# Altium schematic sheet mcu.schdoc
size 277 x 190 mm; Device: default297x210; Symbol: default297x210; Name: default297x210; Size: "A4"; Id: /; File: mcu; Sheet: /
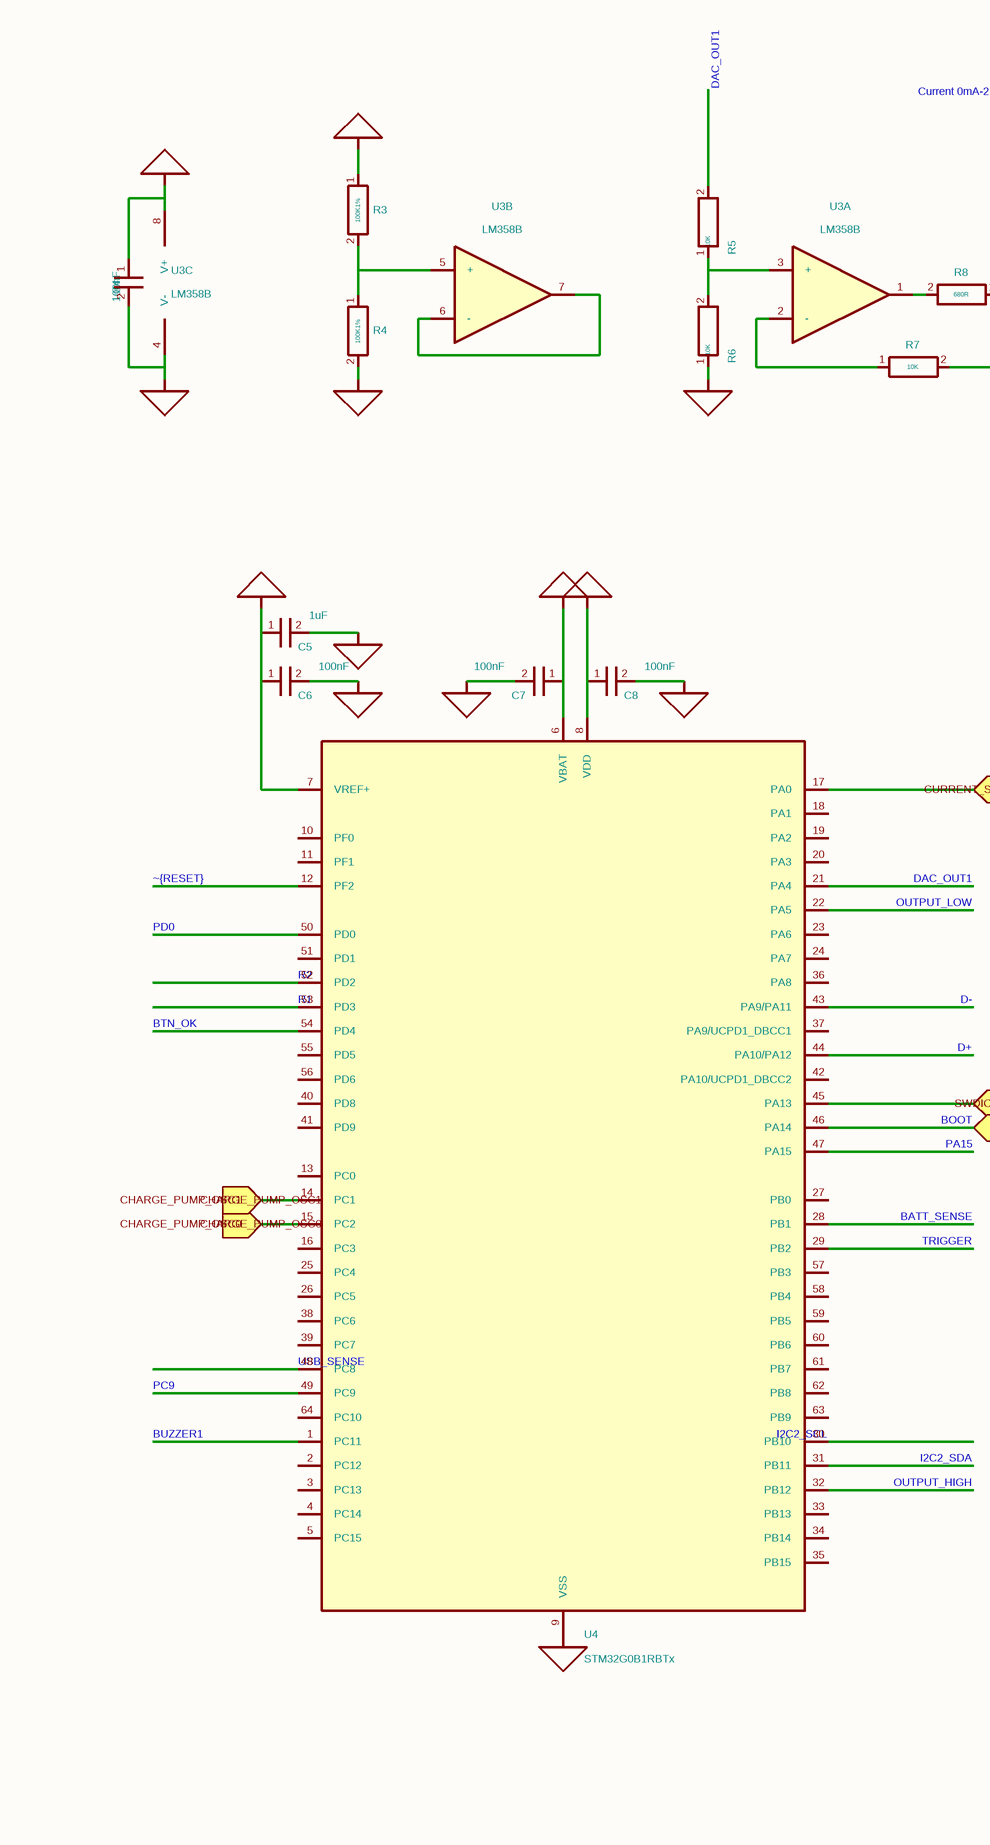
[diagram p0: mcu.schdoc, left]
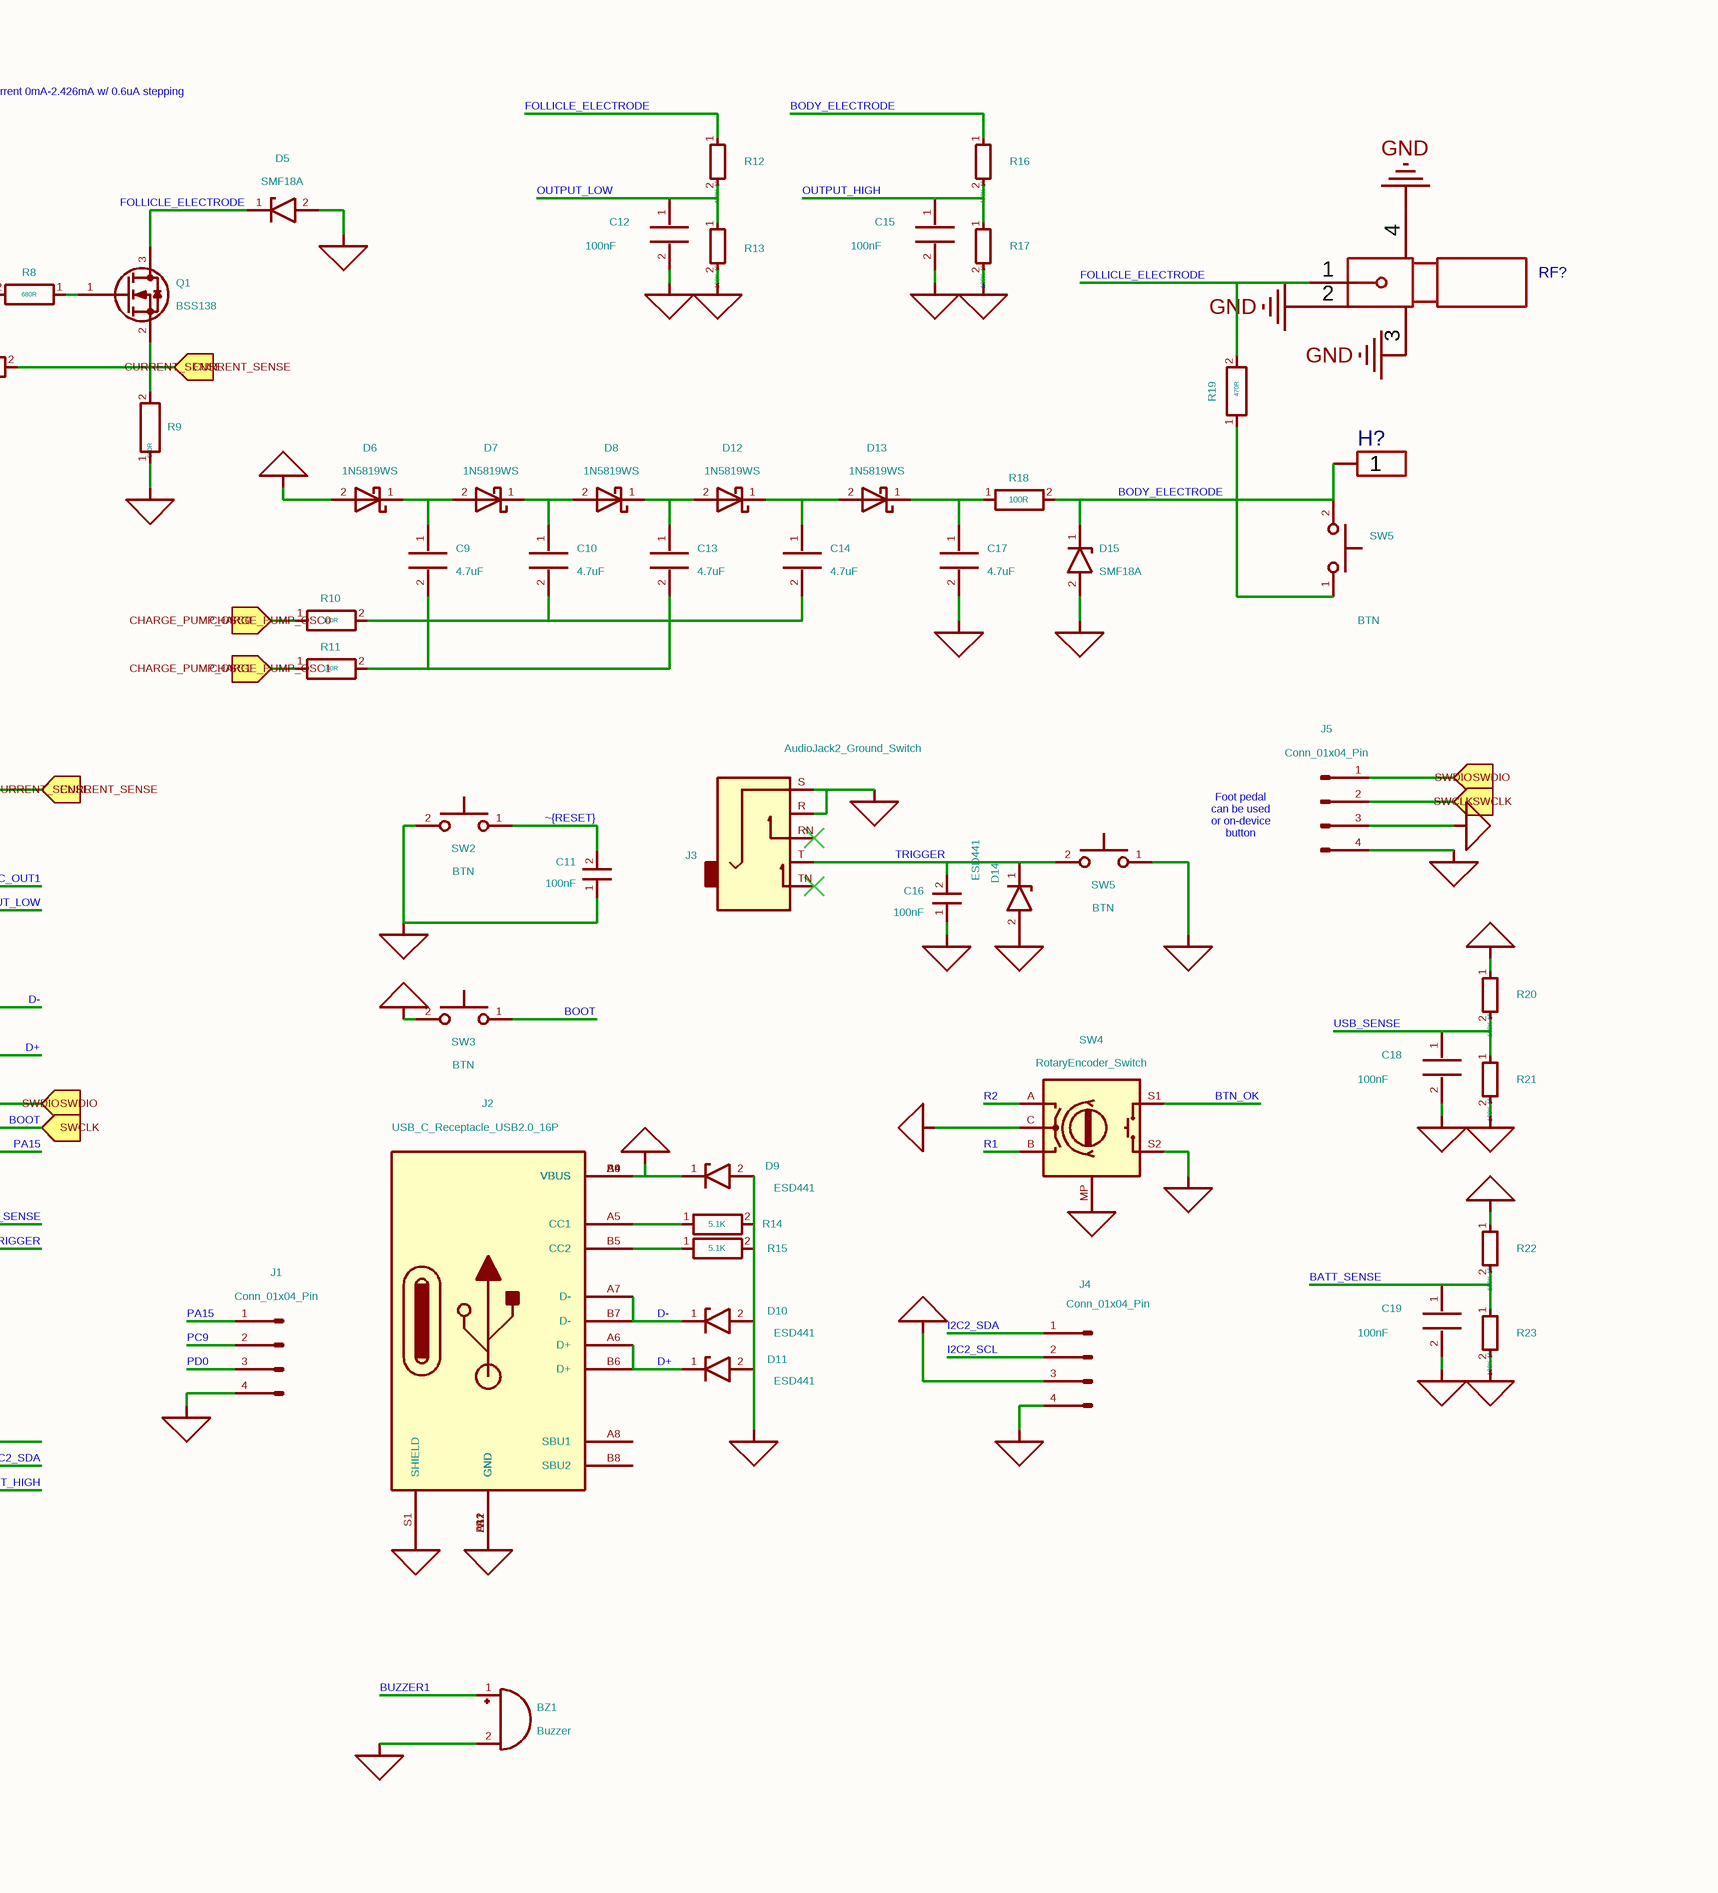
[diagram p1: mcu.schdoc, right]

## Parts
(Parts that share a designator on the sheet are numbered #1, #2 ... from top to bottom, then left to right.)
BZ1  value Buzzer  [Buzzer_Beeper:Buzzer_TDK_PS1240P02BT_D12.2mm_H6.5mm]  (hidden comment: Device_Buzzer)
C4  value 100nF  [Capacitor_SMD:C_0603_1608Metric]  (hidden comment: Device_C_Small)
C5  value 1uF  [Capacitor_SMD:C_0603_1608Metric]  (hidden comment: Device_C_Small)
C6  value 100nF  [Capacitor_SMD:C_0603_1608Metric]  (hidden comment: Device_C_Small)
C7  value 100nF  [Capacitor_SMD:C_0603_1608Metric]  (hidden comment: Device_C_Small)
C8  value 100nF  [Capacitor_SMD:C_0603_1608Metric]  (hidden comment: Device_C_Small)
C9  value 4.7uF  [Capacitor_SMD:C_0805_2012Metric]  (hidden comment: Device_C)
C10  value 4.7uF  [Capacitor_SMD:C_0805_2012Metric]  (hidden comment: Device_C)
C11  value 100nF  [Capacitor_SMD:C_0603_1608Metric]  (hidden comment: Device_C_Small)
C12  value 100nF  [Capacitor_SMD:C_0603_1608Metric]  (hidden comment: Device_C)
C13  value 4.7uF  [Capacitor_SMD:C_0805_2012Metric]  (hidden comment: Device_C)
C14  value 4.7uF  [Capacitor_SMD:C_0805_2012Metric]  (hidden comment: Device_C)
C15  value 100nF  [Capacitor_SMD:C_0603_1608Metric]  (hidden comment: Device_C)
C16  value 100nF  [Capacitor_SMD:C_0603_1608Metric]  (hidden comment: Device_C_Small)
C17  value 4.7uF  [Capacitor_SMD:C_0805_2012Metric]  (hidden comment: Device_C)
C18  value 100nF  [Capacitor_SMD:C_0603_1608Metric]  (hidden comment: Device_C)
C19  value 100nF  [Capacitor_SMD:C_0603_1608Metric]  (hidden comment: Device_C)
D5  value SMF18A  [Diode_SMD:D_SMF]  (hidden comment: Diode_SMF18A)
D6  value 1N5819WS  [Diode_SMD:D_SOD-323]  (hidden comment: Diode_1N5819WS)
D7  value 1N5819WS  [Diode_SMD:D_SOD-323]  (hidden comment: Diode_1N5819WS)
D8  value 1N5819WS  [Diode_SMD:D_SOD-323]  (hidden comment: Diode_1N5819WS)
D9  value ESD441  [Diode_SMD:D_0402_1005Metric]  (hidden comment: Diode_SM6T7V5A)
D10  value ESD441  [Diode_SMD:D_0402_1005Metric]  (hidden comment: Diode_SM6T7V5A)
D11  value ESD441  [Diode_SMD:D_0402_1005Metric]  (hidden comment: Diode_SM6T7V5A)
D12  value 1N5819WS  [Diode_SMD:D_SOD-323]  (hidden comment: Diode_1N5819WS)
D13  value 1N5819WS  [Diode_SMD:D_SOD-323]  (hidden comment: Diode_1N5819WS)
D14  value ESD441  [Diode_SMD:D_0402_1005Metric]  (hidden comment: Diode_SM6T7V5A)
D15  value SMF18A  [Diode_SMD:D_SMF]  (hidden comment: Diode_SMF18A)
H?  (no value)  [HDR-TH_1P-V-M_XKB_X4611WV-01I-C28D40]
J1  value Conn_01x04_Pin  [Connector_PinHeader_2.54mm:PinHeader_1x04_P2.54mm_Vertical]  (hidden comment: Connector_Conn_01x04_Pin)
J2  value USB_C_Receptacle_USB2.0_16P  [Connector_USB:USB_C_Receptacle_HRO_TYPE-C-31-M-12]  (hidden comment: Connector_USB_C_Receptacle_USB2.0_16P)
J3  value AudioJack2_Ground_Switch  [Connector_Audio:Jack_3.5mm_CUI_SJ1-3525N_Horizontal]  (hidden comment: Connector_Audio_AudioJack3_SwitchTR)
J4  value Conn_01x04_Pin  [Connector_PinSocket_2.54mm:PinSocket_1x04_P2.54mm_Vertical]  (hidden comment: Connector_Conn_01x04_Pin)
J5  value Conn_01x04_Pin  [Connector_PinSocket_2.54mm:PinSocket_1x04_P2.54mm_Vertical]  (hidden comment: Connector_Conn_01x04_Pin)
Q1  value BSS138  [Package_TO_SOT_SMD:SOT-23]  (hidden comment: Transistor_FET_BSS138)
R3  value 100K1%  [Resistor_SMD:R_0603_1608Metric_Pad0.98x0.95mm_HandSolder]  (hidden comment: Device_R)
R4  value 100K1%  [Resistor_SMD:R_0603_1608Metric_Pad0.98x0.95mm_HandSolder]  (hidden comment: Device_R)
R5  value 10K  [Resistor_SMD:R_0603_1608Metric_Pad0.98x0.95mm_HandSolder]  (hidden comment: Device_R)
R6  value 10K  [Resistor_SMD:R_0603_1608Metric_Pad0.98x0.95mm_HandSolder]  (hidden comment: Device_R)
R7  value 10K  [Resistor_SMD:R_0603_1608Metric_Pad0.98x0.95mm_HandSolder]  (hidden comment: Device_R)
R8  value 680R  [Resistor_SMD:R_0603_1608Metric_Pad0.98x0.95mm_HandSolder]  (hidden comment: Device_R)
R9  value 680R  [Resistor_SMD:R_0603_1608Metric_Pad0.98x0.95mm_HandSolder]  (hidden comment: Device_R)
R10  value 100R  [Resistor_SMD:R_0603_1608Metric]  (hidden comment: Device_R)
R11  value 100R  [Resistor_SMD:R_0603_1608Metric]  (hidden comment: Device_R)
R12  value 470K 1%  [Resistor_SMD:R_0603_1608Metric]  (hidden comment: Device_R_Small)
R13  value 100K 1%  [Resistor_SMD:R_0603_1608Metric]  (hidden comment: Device_R_Small)
R14  value 5.1K  [Resistor_SMD:R_0603_1608Metric]  (hidden comment: Device_R)
R15  value 5.1K  [Resistor_SMD:R_0603_1608Metric]  (hidden comment: Device_R)
R16  value 470K 1%  [Resistor_SMD:R_0603_1608Metric]  (hidden comment: Device_R_Small)
R17  value 100K 1%  [Resistor_SMD:R_0603_1608Metric]  (hidden comment: Device_R_Small)
R18  value 100R  [Resistor_SMD:R_0603_1608Metric]  (hidden comment: Device_R)
R19  value 470R  [Resistor_SMD:R_0603_1608Metric_Pad0.98x0.95mm_HandSolder]  (hidden comment: Device_R)
R20  value 100K 1%  [Resistor_SMD:R_0603_1608Metric]  (hidden comment: Device_R_Small)
R21  value 100K 1%  [Resistor_SMD:R_0603_1608Metric]  (hidden comment: Device_R_Small)
R22  value 100K 1%  [Resistor_SMD:R_0603_1608Metric]  (hidden comment: Device_R_Small)
R23  value 100K 1%  [Resistor_SMD:R_0603_1608Metric]  (hidden comment: Device_R_Small)
RF?  3GHz  [BNC-TH_DOSIN-801-0030]  (value not drawn)
SW2  value BTN  [Button_Switch_SMD:SW_SPST_TS-1088-xR025]  (hidden comment: Switch_SW_Push)
SW3  value BTN  [Button_Switch_SMD:SW_SPST_TS-1088-xR025]  (hidden comment: Switch_SW_Push)
SW4  value RotaryEncoder_Switch  [Rotary_Encoder:RotaryEncoder_Alps_EC11E-Switch_Vertical_H20mm]  (hidden comment: Device_RotaryEncoder_Switch)
SW5#1  value BTN  [Button_Switch_SMD:SW_SPST_TS-1088-xR025]  (hidden comment: Switch_SW_Push)
SW5#2  value BTN  [Button_Switch_SMD:SW_SPST_TS-1088-xR025]  (hidden comment: Switch_SW_Push)
U3  value LM358B  [Package_SO:SOIC-8_3.9x4.9mm_P1.27mm]  (hidden comment: Amplifier_Operational_LM358)  (parts A,B,C of 3)
U4  value STM32G0B1RBTx  [Package_QFP:LQFP-64_10x10mm_P0.5mm]  (hidden comment: MCU_ST_STM32G0_STM32G0B1RBTx)

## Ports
CHARGE_PUMP_OSC0 (in), CHARGE_PUMP_OSC1 (in), CURRENT_SENSE (in), SWCLK (in), SWDIO (in)

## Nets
GND: RF?.2 RF?.3 RF?.4
power_+3.3V: C5.1 C6.1 C7.1 C8.1 D6.2(A) J4.3(Pin_3) J5.3(Pin_3) SW3.2 U4.6(VBAT) U4.7(VREF+) U4.8(VDD)
power_+5V: D9.1(A1) J2.A4(VBUS) J2.A9(VBUS) J2.B4(VBUS) J2.B9(VBUS)
power_+BATT: C4.1 R3.1 R22.1 U3.8(V+)
power_GND: BZ1.2(-) C4.2 C5.2 C6.2 C7.2 C8.2 C11.1 C12.2 C15.2 C16.1 C17.2 C18.2 C19.2 D5.2(A2) D9.2(A2) D10.2(A2) D11.2(A2) D14.2(A2) D15.2(A2) J1.4(Pin_4) J2.A1(GND) J2.A12(GND) J2.B1(GND) J2.B12(GND) J2.S1(SHIELD) J3.R J3.S J4.4(Pin_4) J5.4(Pin_4) R4.2 R6.1 R9.1 R13.2 R14.2 R15.2 R17.2 R21.2 R23.2 SW2.2 SW4.C SW4.MP SW4.S2 SW5#2.1 U3.4(V-) U4.9(VSS)
power_VBUS: R20.1
BATT_SENSE: C19.1 R22.2 R23.1 U4.28(PB1)
BODY_ELECTRODE: D15.1(A1) H?.1 R16.1 R18.2 SW5#1.2
BOOT: J5.2(Pin_2) SW3.1 U4.46(PA14) ; port SWCLK  [also labelled SWCLK]
BTN_OK: SW4.S1 U4.54(PD4)
BUZZER1: BZ1.1(+) U4.1(PC11)
CHARGE_PUMP_OSC0: R10.1 U4.15(PC2) ; port CHARGE_PUMP_OSC0
CHARGE_PUMP_OSC1: R11.1 U4.14(PC1) ; port CHARGE_PUMP_OSC1
CURRENT_SENSE: Q1.2(S) R7.2 R9.2 U4.17(PA0) ; port CURRENT_SENSE
D+: D11.1(A1) J2.A6(D+) J2.B6(D+) U4.44(PA10/PA12)
D-: D10.1(A1) J2.A7(D-) J2.B7(D-) U4.43(PA9/PA11)
DAC_OUT1: R5.2 U4.21(PA4)
FOLLICLE_ELECTRODE: D5.1(A1) Q1.3(D) R12.1 R19.2 RF?.1
I2C2_SCL: J4.2(Pin_2) U4.30(PB10)
I2C2_SDA: J4.1(Pin_1) U4.31(PB11)
OUTPUT_HIGH: C15.1 R16.2 R17.1 U4.32(PB12)
OUTPUT_LOW: C12.1 R12.2 R13.1 U4.22(PA5)
PA15: J1.1(Pin_1) U4.47(PA15)
PC9: J1.2(Pin_2) U4.49(PC9)
PD0: J1.3(Pin_3) U4.50(PD0)
R1: SW4.B U4.53(PD3)
R2: SW4.A U4.52(PD2)
SWDIO: J5.1(Pin_1) U4.45(PA13) ; port SWDIO
TRIGGER: C16.2 D14.1(A1) J3.T SW5#2.2 U4.29(PB2)
USB_SENSE: C18.1 R20.2 R21.1 U4.48(PC8)
~{RESET}: C11.2 SW2.1 U4.12(PF2)
NetC9_1: C9.1 D6.1(K) D7.2(A)
NetC9_2: C9.2 C13.2 R11.2
NetC10_1: C10.1 D7.1(K) D8.2(A)
NetC10_2: C10.2 C14.2 R10.2
NetC13_1: C13.1 D8.1(K) D12.2(A)
NetC14_1: C14.1 D12.1(K) D13.2(A)
NetC17_1: C17.1 D13.1(K) R18.1
NetJ2_A5: J2.A5(CC1) R14.1
NetJ2_B5: J2.B5(CC2) R15.1
NetQ1_1: Q1.1(G) R8.1
NetR3_2: R3.2 R4.1 U3.5(+)
NetR5_1: R5.1 R6.2 U3.3(+)
NetR7_1: R7.1 U3.2(-)
NetR8_2: R8.2 U3.1
NetR19_1: R19.1 SW5#1.1
NetU3_6: U3.6(-) U3.7

Not connected (* = marked no-connect by the designer): J2 A8(SBU1) B8(SBU2); J3 RN* TN*; U4 2(PC12) 3(PC13) 4(PC14) 5(PC15) 10(PF0) 11(PF1) 13(PC0) 16(PC3) 18(PA1) 19(PA2) 20(PA3) 23(PA6) 24(PA7) 25(PC4) 26(PC5) 27(PB0) 33(PB13) 34(PB14) 35(PB15) 36(PA8) 37(PA9/UCPD1_DBCC1) 38(PC6) 39(PC7) 40(PD8) 41(PD9) 42(PA10/UCPD1_DBCC2) 51(PD1) 55(PD5) 56(PD6) 57(PB3) 58(PB4) 59(PB5) 60(PB6) 61(PB7) 62(PB8) 63(PB9) 64(PC10)

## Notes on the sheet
- Current 0mA-2.426mA w/ 0.6uA stepping
- Foot pedal
  can be used
  or on-device
  button

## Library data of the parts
BZ1 = Device_Buzzer: ki_fp_filters: *Buzzer*; UniqueId: a79a1bda820114ad; Attribute1: BZ1; AddInBom: yes
C4 = Device_C_Small: Unpolarized capacitor, small symbol; ki_fp_filters: C_*; UniqueId: 3a68d3ddabf48558; Attribute1: C6; AddInBom: yes
C5 = Device_C_Small: Unpolarized capacitor, small symbol; ki_fp_filters: C_*; UniqueId: ddba3c46cf8b8e66; Attribute1: C6; AddInBom: yes
C6 = Device_C_Small: Unpolarized capacitor, small symbol; ki_fp_filters: C_*; UniqueId: ab4a8fe24fad9fe4; Attribute1: C6; AddInBom: yes
C7 = Device_C_Small: Unpolarized capacitor, small symbol; ki_fp_filters: C_*; UniqueId: 48d2dd422533522c; Attribute1: C6; AddInBom: yes
C8 = Device_C_Small: Unpolarized capacitor, small symbol; ki_fp_filters: C_*; UniqueId: 80f3708378e3d903; Attribute1: C6; AddInBom: yes
C9 = Device_C: Unpolarized capacitor; UniqueId: 7ddfd2f632a8b17d; AddInBom: yes
C10 = Device_C: Unpolarized capacitor; UniqueId: 3e75135af30e0f04; AddInBom: yes
C11 = Device_C_Small: Unpolarized capacitor, small symbol; ki_fp_filters: C_*; UniqueId: 20764de07767b3a1; Attribute1: C6; AddInBom: yes
C12 = Device_C: Unpolarized capacitor; UniqueId: 26a39bcafcc8ce7c; AddInBom: yes
C13 = Device_C: Unpolarized capacitor; UniqueId: e7ba3aba9f9889c8; AddInBom: yes
C14 = Device_C: Unpolarized capacitor; UniqueId: 00361082df9d4549; AddInBom: yes
C15 = Device_C: Unpolarized capacitor; UniqueId: 86bb77bda672094d; AddInBom: yes
C16 = Device_C_Small: Unpolarized capacitor, small symbol; ki_fp_filters: C_*; UniqueId: c8e923f96b539988; Attribute1: C6; AddInBom: yes
C17 = Device_C: Unpolarized capacitor; UniqueId: 48700c84863a802e; AddInBom: yes
C18 = Device_C: Unpolarized capacitor; UniqueId: d9d0285421fe3ef0; AddInBom: yes
C19 = Device_C: Unpolarized capacitor; UniqueId: 9b75bd895f0e39d2; AddInBom: yes
D5 = Diode_SMF18A: 200W unidirectional Transil Transient Voltage Suppressor, 18Vrwm, SMF; ki_fp_filters: D*SMF*; UniqueId: aa27cf4c2f614704; Attribute1: D15; AddInBom: yes
D6 = Diode_1N5819WS: 40V 600mV@1A 1A SOD-323 Schottky Barrier Diodes, SOD-323; ki_fp_filters: D*SOD?323*; UniqueId: 0b466d7a0d9696a1; Attribute1: D6; AddInBom: yes
D7 = Diode_1N5819WS: 40V 600mV@1A 1A SOD-323 Schottky Barrier Diodes, SOD-323; ki_fp_filters: D*SOD?323*; UniqueId: 61ba849a9213f6b6; Attribute1: D6; AddInBom: yes
D8 = Diode_1N5819WS: 40V 600mV@1A 1A SOD-323 Schottky Barrier Diodes, SOD-323; ki_fp_filters: D*SOD?323*; UniqueId: d726a396729c3148; Attribute1: D6; AddInBom: yes
D9 = Diode_SM6T7V5A: ki_fp_filters: D*SMB*; UniqueId: ff0c81595de38f51; Attribute1: D9; AddInBom: yes
D10 = Diode_SM6T7V5A: ki_fp_filters: D*SMB*; UniqueId: 260e63abbc5bbcdd; Attribute1: D9; AddInBom: yes
D11 = Diode_SM6T7V5A: ki_fp_filters: D*SMB*; UniqueId: 63002c75ba05748a; Attribute1: D9; AddInBom: yes
D12 = Diode_1N5819WS: 40V 600mV@1A 1A SOD-323 Schottky Barrier Diodes, SOD-323; ki_fp_filters: D*SOD?323*; UniqueId: a80f7d1f54f711b8; Attribute1: D6; AddInBom: yes
D13 = Diode_1N5819WS: 40V 600mV@1A 1A SOD-323 Schottky Barrier Diodes, SOD-323; ki_fp_filters: D*SOD?323*; UniqueId: d3460379f3d05a2a; Attribute1: D6; AddInBom: yes
D14 = Diode_SM6T7V5A: ki_fp_filters: D*SMB*; UniqueId: f1c346e37d3cba37; Attribute1: D9; AddInBom: yes
D15 = Diode_SMF18A: 200W unidirectional Transil Transient Voltage Suppressor, 18Vrwm, SMF; ki_fp_filters: D*SMF*; UniqueId: ff96faf82be08131; Attribute1: D15; AddInBom: yes
H? = HDR-M_2.54_1x1P: Symbol: HDR_1x1; AddInBom: yes; ModelId: 728f8802f5b64d9eac2f12b79a6c354c0819f05c4eef4c71ace90d822a990e87; ModelTransform: 78.74,79.1337,0,0,0,0,0,0,-110.236
J1 = Connector_Conn_01x04_Pin: Generic connector, single row, 01x04, script generated; ki_fp_filters: Connector*:*_1x??_*; UniqueId: 51bfc0e5166a1c40; Attribute1: J1; AddInBom: yes
J2 = Connector_USB_C_Receptacle_USB2.0_16P: USB 2.0-only 16P Type-C Receptacle connector; ki_fp_filters: USB*C*Receptacle*; UniqueId: 1fb9863844ab5169; Attribute1: J2; AddInBom: yes
J3 = Connector_Audio_AudioJack3_SwitchTR: Audio Jack, 3 Poles (Stereo / TRS), Switched TR Poles (Normalling); ki_fp_filters: Jack*; UniqueId: bd3ee0abdb58119f; Attribute1: PCB edge; Attribute2: J3; AddInBom: yes
J4 = Connector_Conn_01x04_Pin: Generic connector, single row, 01x04, script generated; ki_fp_filters: Connector*:*_1x??_*; UniqueId: 7aadee231938cadd; Attribute1: J4; KiLib_Generator: connector/pin_header_socket; AddInBom: yes
J5 = Connector_Conn_01x04_Pin: Generic connector, single row, 01x04, script generated; ki_fp_filters: Connector*:*_1x??_*; UniqueId: 188f82074eb8ca32; Attribute1: J4; KiLib_Generator: connector/pin_header_socket; AddInBom: yes
Q1 = Transistor_FET_BSS138: 50V Vds, 0.22A Id, N-Channel MOSFET, SOT-23; ki_fp_filters: SOT?23*; UniqueId: f76c01de5337d462; Attribute1: Q1; AddInBom: yes
R3 = Device_R: Resistor; ki_fp_filters: R_*; UniqueId: fe89d0632cfce75f; Attribute1: R7; KiLib_Generator: SMD_2terminal_chip_molded; AddInBom: yes
R4 = Device_R: Resistor; ki_fp_filters: R_*; UniqueId: fdc86a4b576d9e98; Attribute1: R7; KiLib_Generator: SMD_2terminal_chip_molded; AddInBom: yes
R5 = Device_R: Resistor; ki_fp_filters: R_*; UniqueId: 9cdd622c9eeecfe7; Attribute1: R7; KiLib_Generator: SMD_2terminal_chip_molded; AddInBom: yes
R6 = Device_R: Resistor; ki_fp_filters: R_*; UniqueId: e06ccd13940482ac; Attribute1: R7; KiLib_Generator: SMD_2terminal_chip_molded; AddInBom: yes
R7 = Device_R: Resistor; ki_fp_filters: R_*; UniqueId: ba2c6d155e7fd301; Attribute1: R7; KiLib_Generator: SMD_2terminal_chip_molded; AddInBom: yes
R8 = Device_R: Resistor; ki_fp_filters: R_*; UniqueId: 86d447fa2a9c8586; Attribute1: R7; KiLib_Generator: SMD_2terminal_chip_molded; AddInBom: yes
R9 = Device_R: Resistor; ki_fp_filters: R_*; UniqueId: 1e1ffada38203b9e; Attribute1: R7; KiLib_Generator: SMD_2terminal_chip_molded; AddInBom: yes
R10 = Device_R: Resistor; UniqueId: 41bc0941336b1513; AddInBom: yes
R11 = Device_R: Resistor; UniqueId: 763cf8d5648cb4fd; AddInBom: yes
R12 = Device_R_Small: Resistor, small symbol; ki_fp_filters: R_*; UniqueId: 15ac9218146e0f4b; Attribute1: R16; AddInBom: yes
R13 = Device_R_Small: Resistor, small symbol; ki_fp_filters: R_*; UniqueId: ff4077a9ca69db92; Attribute1: R16; AddInBom: yes
R14 = Device_R: Resistor; UniqueId: 8b54177fc4d64d35; AddInBom: yes
R15 = Device_R: Resistor; UniqueId: feece054417b9159; AddInBom: yes
R16 = Device_R_Small: Resistor, small symbol; ki_fp_filters: R_*; UniqueId: 3c543c7c58e1cc80; Attribute1: R16; AddInBom: yes
R17 = Device_R_Small: Resistor, small symbol; ki_fp_filters: R_*; UniqueId: 6346d187b4e0bc9c; Attribute1: R16; AddInBom: yes
R18 = Device_R: Resistor; UniqueId: 5f673669f0d56d8f; AddInBom: yes
R19 = Device_R: Resistor; ki_fp_filters: R_*; UniqueId: a32210a39874d8f8; Attribute1: R7; KiLib_Generator: SMD_2terminal_chip_molded; AddInBom: yes
R20 = Device_R_Small: Resistor, small symbol; ki_fp_filters: R_*; UniqueId: 13e77c54ede4b306; Attribute1: R16; AddInBom: yes
R21 = Device_R_Small: Resistor, small symbol; ki_fp_filters: R_*; UniqueId: c77b08197b178948; Attribute1: R16; AddInBom: yes
R22 = Device_R_Small: Resistor, small symbol; ki_fp_filters: R_*; UniqueId: fa394caafc8878d8; Attribute1: R16; AddInBom: yes
R23 = Device_R_Small: Resistor, small symbol; ki_fp_filters: R_*; UniqueId: d92c635076b33213; Attribute1: R16; AddInBom: yes
RF? = DOSIN-801-0031: Connector Type:Board Side Interface:Inner hole Number of Ports:1 Interface Diameter:11mm Interface Length/Height:35.7mm Frequency:3GHz RF Series:BNC Impedance:75Ω Style:Elbow Rated Voltage (Max):500V Operating Temperature Range:-55℃~+155℃ Operating Temper; Manufacturer: dosinconn(德索五金); AddInBom: yes; ModelId: 3bfecaa8a5924dd8a4e4ce7c1639d24c0819f05c4eef4c71ace90d822a990e87; ModelTransform: 578.739,1397.635,0,0,0,0,-0.001,555.116,-165.354; Number of Ports: 1; Interface Diameter: 11mm; Interface Length/Height: 35.7mm; RF Series: BNC; Impedance: 75Ω; Style: Elbow; Rated Voltage (Max): 500V
SW2 = Switch_SW_Push: Push button switch, generic, two pins; UniqueId: 5cf9f4a776b330ee; Attribute1: SW5; AddInBom: yes
SW3 = Switch_SW_Push: Push button switch, generic, two pins; UniqueId: 2f7d3d657bff299d; Attribute1: SW5; AddInBom: yes
SW4 = Device_RotaryEncoder_Switch: Rotary encoder, dual channel, incremental quadrate outputs, with switch; ki_fp_filters: RotaryEncoder*Switch*; UniqueId: a09384242b90f9e9; Attribute1: SW4; AddInBom: yes
SW5#1 = Switch_SW_Push: Push button switch, generic, two pins; Attribute1: SW5; AddInBom: yes
SW5#2 = Switch_SW_Push: Push button switch, generic, two pins; UniqueId: 827e4a881924ffc6; Attribute1: SW5; AddInBom: yes
U3 = Amplifier_Operational_LM358: Low-Power, Dual Operational Amplifiers, DIP-8/SOIC-8/TO-99-8; ki_fp_filters: SOIC*3.9x4.9mm*P1.27mm* DIP*W7.62mm* TO*99* OnSemi*Micro8* TSSOP*3x3mm*P0.65mm* TSSOP*4.4x3mm*P0.65mm* MSOP*3x3mm*P0.65mm* SSOP*3.9x4.9mm*P0.635mm* LFCSP*2x2mm*P0.5mm* *SIP* SOIC*5.3x6.2mm*P1.27mm*; UniqueId: 66797bcd97f4f6c2; Attribute1: U3; AddInBom: yes
U4 = MCU_ST_STM32G0_STM32G0B1RBTx: STMicroelectronics Arm Cortex-M0+ MCU, 128KB flash, 144KB RAM, 64 MHz, 1.7-3.6V, 60 GPIO, LQFP64; ki_fp_filters: LQFP*10x10mm*P0.5mm*; UniqueId: bac468049775df37; Attribute1: U4; KiLib_Generator: package/gullwing; AddInBom: yes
